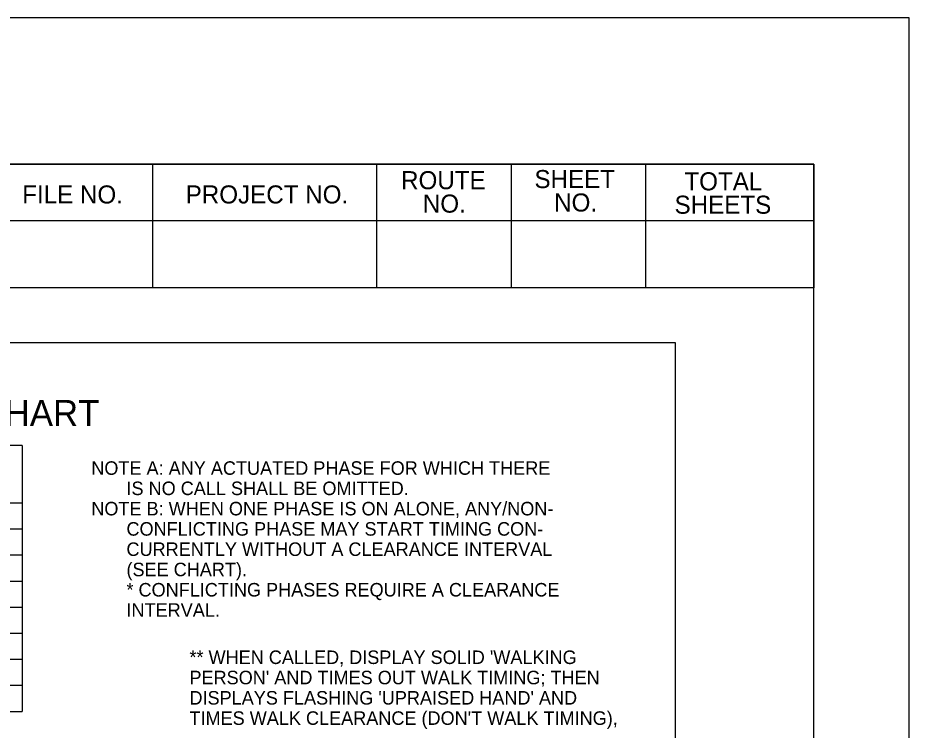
# Model space of a CAD drawing. Extents: x 0 to 3.01, y -0.05 to 1.83.
# Drawn here: x 2.6475 to 3, y 1.5516 to 1.8333 of the extents above; entities that cross this region are included whole.
import ezdxf

# ---------------------------------------------------------------- set-up
doc = ezdxf.new("R2010")
doc.units = 0
doc.layers.add('RD_SHT_IplotShp', color=7, linetype='Continuous')
doc.layers.add('TR_TS_Border', color=7, linetype='Continuous')

msp = doc.modelspace()

# ---------------------------------------------------------------- linework, layer by layer
at = {"layer": 'RD_SHT_IplotShp'}
msp.add_lwpolyline([(-3.9736429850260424e-10, -8.265177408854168e-09), (3.0000020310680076, -8.265177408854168e-09), (3.0000020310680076, 1.8333311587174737), (-3.9736429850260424e-10, 1.8333311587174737)], close=True, dxfattribs=at)
at = {"layer": 'TR_TS_Border'}
for p, q in [((2.9712428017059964, 1.8333311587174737), (0.03100253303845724, 1.8333311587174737)), ((3.0000020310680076, -8.265177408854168e-09), (3.0000020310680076, 1.8333311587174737)), ((2.9623464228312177, 1.775395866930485), (0.16861088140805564, 1.775395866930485)), ((2.7008295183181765, 1.7266175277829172), (2.7008295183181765, 1.775395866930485)), ((2.789485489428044, 1.7266175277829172), (2.789485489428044, 1.775395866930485)), ((2.8427144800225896, 1.7266175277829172), (2.8427144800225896, 1.775395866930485)), ((2.8958545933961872, 1.7266175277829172), (2.8958545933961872, 1.775395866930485)), ((2.9623464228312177, 0.04746643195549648), (2.9623464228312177, 1.775395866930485)), ((2.4304114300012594, 1.7532322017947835), (2.9623464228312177, 1.7532322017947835)), ((2.2983738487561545, 1.7049511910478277), (2.9074767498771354, 1.7049511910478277)), ((2.9074767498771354, 1.7049511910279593), (2.9074766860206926, 1.275593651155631)), ((2.64920180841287, 1.6642387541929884), (2.4639501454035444, 1.6642387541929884)), ((2.64920180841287, 1.6642387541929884), (2.64920180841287, 1.559062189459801)), ((2.4639501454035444, 1.6415234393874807), (2.64920180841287, 1.6415234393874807)), ((2.4639501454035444, 1.6312160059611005), (2.64920180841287, 1.6312160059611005)), ((2.4639501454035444, 1.6209083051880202), (2.64920180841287, 1.6209083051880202)), ((2.4639501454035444, 1.6106005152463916), (2.64920180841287, 1.6106005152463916)), ((2.4639501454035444, 1.6002929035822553), (2.64920180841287, 1.6002929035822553)), ((2.4639501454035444, 1.5899851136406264), (2.64920180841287, 1.5899851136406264)), ((2.4639501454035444, 1.57967741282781), (2.64920180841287, 1.57967741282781)), ((2.4639501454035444, 1.5693698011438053), (2.64920180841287, 1.5693698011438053)), ((2.4639501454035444, 1.559062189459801), (2.64920180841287, 1.559062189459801))]:
    msp.add_line(p, q, dxfattribs=at)
msp.add_lwpolyline([(2.9623464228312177, 1.775395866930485), (2.9623464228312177, 1.7266175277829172), (2.4304114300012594, 1.7266175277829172), (2.4304114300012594, 1.775395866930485)], close=True, dxfattribs=at)

# ---------------------------------------------------------------- texts
for s, height, p in [('SHEET', 0.007148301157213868, (2.8518080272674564, 1.7659877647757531)), ('ROUTE', 0.007148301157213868, (2.79905529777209, 1.7655446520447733)), ('TOTAL', 0.007148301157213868, (2.9111041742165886, 1.765101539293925)), ('FILE NO.', 0.007148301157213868, (2.6492106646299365, 1.7599132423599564)), ('PROJECT NO.', 0.007148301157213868, (2.713872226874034, 1.7599132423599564)), ('NO.', 0.007148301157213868, (2.80765832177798, 1.7562932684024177)), ('NO.', 0.007148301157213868, (2.8595828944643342, 1.7567363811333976)), ('SHEETS', 0.007148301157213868, (2.9072140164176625, 1.7558501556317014)), ('SIGNAL DISPLAY SEQUENCE CHART', 0.0102810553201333, (2.43524737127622, 1.6719141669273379)), ('NOTE A: ANY ACTUATED PHASE FOR WHICH THERE', 0.005346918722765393, (2.6765385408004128, 1.6526063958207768)), ('       IS NO CALL SHALL BE OMITTED.', 0.005346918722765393, (2.6765385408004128, 1.6445860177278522)), ('NOTE B: WHEN ONE PHASE IS ON ALONE, ANY/NON-', 0.005346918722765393, (2.6765385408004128, 1.6365656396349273)), ('       CONFLICTING PHASE MAY START TIMING CON-', 0.005346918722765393, (2.6765385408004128, 1.6285452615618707)), ('       CURRENTLY WITHOUT A CLEARANCE INTERVAL', 0.005346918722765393, (2.6765385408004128, 1.6205248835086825)), ('       (SEE CHART).', 0.005346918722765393, (2.6765385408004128, 1.6125045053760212)), ('       * CONFLICTING PHASES REQUIRE A CLEARANCE', 0.005346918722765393, (2.6765385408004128, 1.6044841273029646)), ('       INTERVAL.', 0.005346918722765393, (2.6765385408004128, 1.5964637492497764)), ("** WHEN CALLED, DISPLAY SOLID 'WALKING ", 0.005346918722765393, (2.7153579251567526, 1.5777893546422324)), ("PERSON' AND TIMES OUT WALK TIMING; THEN ", 0.005346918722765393, (2.7153579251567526, 1.5697689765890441)), ("DISPLAYS FLASHING 'UPRAISED HAND' AND ", 0.005346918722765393, (2.7153579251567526, 1.5617485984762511)), ("TIMES WALK CLEARANCE (DON'T WALK TIMING), ", 0.005346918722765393, (2.7153579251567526, 1.553728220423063))]:
    msp.add_text(s, height=height, dxfattribs=at).set_placement(p)

doc.saveas('drawing.dxf')
